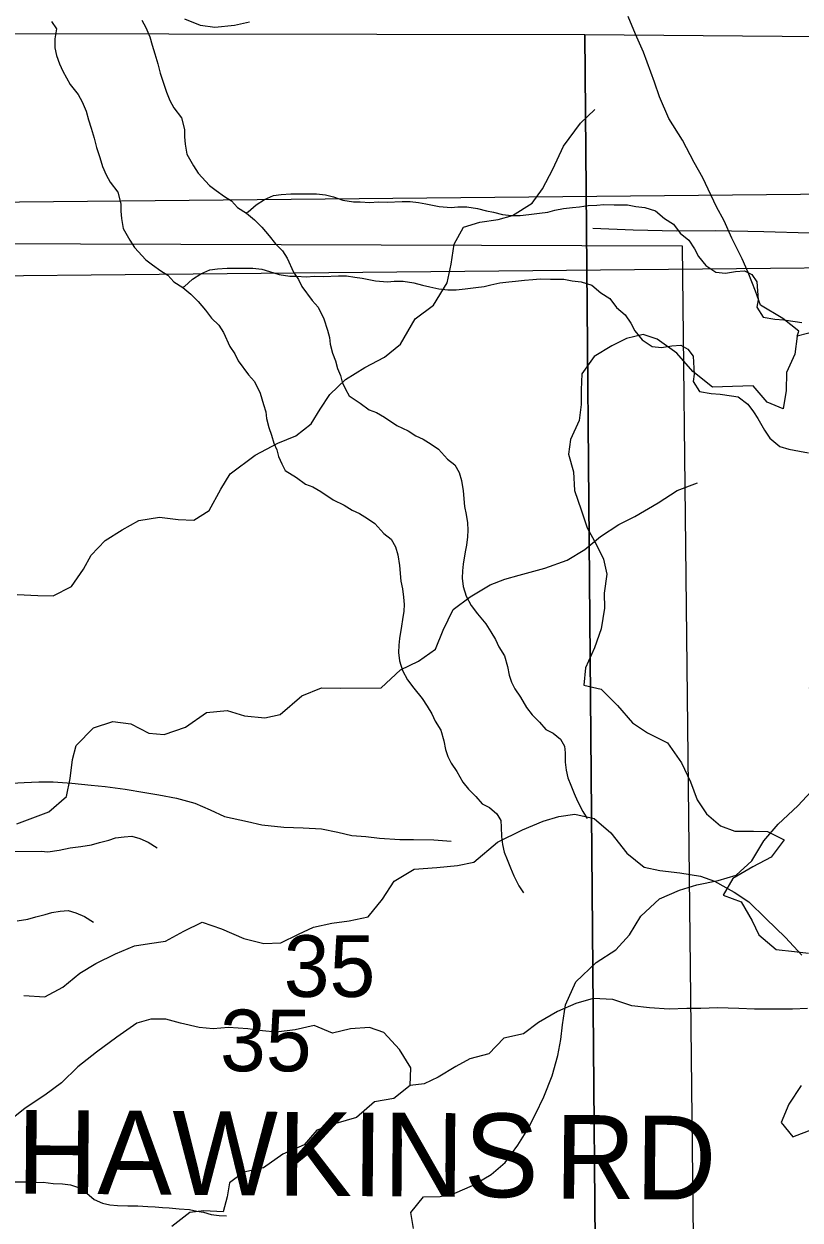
# Model space of a CAD drawing. Extents: x -21.1 to 50.3, y 0 to 22.1.
# Drawn here: x 7.069 to 7.596, y 19.342 to 20.155 of the extents above; entities that cross this region are included whole.
import ezdxf

# ---------------------------------------------------------------- set-up
doc = ezdxf.new("R2010")
doc.units = 0
for name, color, linetype in [('GM_X_City_Street', 7, 'Continuous'), ('GM_X_Major_Lake', 7, 'Continuous'), ('GM_X_Minor_River', 7, 'Continuous'), ('GM_X_Section', 7, 'Continuous'), ('GM_X_Section_Text', 7, 'Continuous'), ('GM_X_Township_Road_Text', 7, 'Continuous')]:
    doc.layers.add(name, color=color, linetype=linetype)

msp = doc.modelspace()

# ---------------------------------------------------------------- linework, layer by layer
at = {"layer": 'GM_X_City_Street'}
msp.add_lwpolyline([(7.45524, 20.01596), (7.48275, 20.01484), (7.51234, 20.01417), (7.53874, 20.01437), (7.57151, 20.01373), (7.60253, 20.01277), (7.652, 20.01277), (7.66218, 20.01262), (7.69033, 20.01023), (7.70354, 20.00864), (7.71849, 20.00673), (7.72771, 20.0053), (7.7573, 20.00403), (7.80725, 20.00418)], dxfattribs=at)
at = {"layer": 'GM_X_Major_Lake'}
for points in [[(7.60818, 19.94633), (7.59416, 19.94253), (7.59263, 19.9304), (7.58694, 19.91788), (7.58656, 19.90574), (7.58465, 19.89323), (7.57366, 19.89778), (7.56419, 19.90877), (7.55017, 19.90839), (7.53652, 19.90801), (7.52326, 19.91863), (7.51227, 19.93115), (7.49901, 19.94062), (7.48954, 19.94366), (7.47816, 19.941), (7.4683, 19.93607), (7.45617, 19.92886), (7.44783, 19.9171), (7.44744, 19.90611), (7.44743, 19.89624), (7.44591, 19.88525), (7.44022, 19.87235), (7.4387, 19.86249), (7.4421, 19.85035), (7.44285, 19.83783), (7.4474, 19.82456)], [(7.4474, 19.82456), (7.45156, 19.81243), (7.45762, 19.80143), (7.46254, 19.79119), (7.46481, 19.78095), (7.46291, 19.76805), (7.46328, 19.75781), (7.461, 19.74378), (7.45644, 19.73088), (7.45037, 19.71723), (7.44923, 19.70547), (7.46098, 19.70282), (7.47196, 19.69182), (7.48219, 19.68006), (7.49242, 19.67324), (7.50606, 19.66641), (7.51553, 19.65276), (7.52159, 19.63987), (7.52613, 19.62773), (7.53257, 19.61825), (7.54204, 19.6099), (7.5519, 19.60649), (7.56441, 19.60649), (7.57388, 19.60612), (7.58525, 19.60043), (7.57653, 19.58867), (7.56402, 19.58222), (7.55036, 19.57426), (7.54392, 19.56288), (7.55604, 19.55833), (7.56362, 19.54543), (7.56816, 19.53595), (7.57991, 19.52609), (7.59242, 19.52458), (7.60189, 19.52344)], [(7.59691, 19.43355), (7.58857, 19.42103), (7.58325, 19.40852), (7.59121, 19.39866), (7.60486, 19.40397)]]:
    msp.add_lwpolyline(points, dxfattribs=at)
at = {"layer": 'GM_X_Minor_River'}
for points in [[(7.59416, 19.94253), (7.59529, 19.94595), (7.58431, 19.95467), (7.56915, 19.96377), (7.56574, 19.97325), (7.56082, 19.98576), (7.55666, 19.99525), (7.54984, 20.00928), (7.54454, 20.02103), (7.53924, 20.03052), (7.53015, 20.05024), (7.52409, 20.06048), (7.51614, 20.07565), (7.50705, 20.09044), (7.50062, 20.10523), (7.49721, 20.11509), (7.48964, 20.13557), (7.48434, 20.1477), (7.47942, 20.15984)], [(7.08744, 20.1564), (7.09089, 20.15149), (7.08978, 20.14464), (7.08982, 20.13856), (7.09099, 20.13325), (7.09293, 20.12756), (7.09524, 20.12264), (7.10024, 20.11355), (7.1056, 20.10674), (7.1083, 20.10181), (7.111, 20.09537), (7.11255, 20.08968), (7.11449, 20.08399), (7.11643, 20.07717), (7.11799, 20.07072), (7.12031, 20.06389), (7.12224, 20.05782), (7.12456, 20.05214), (7.12725, 20.04721), (7.13262, 20.0404), (7.13457, 20.03244), (7.1346, 20.0275), (7.135, 20.02256), (7.13618, 20.01573), (7.14079, 20.00778), (7.14387, 20.00286), (7.15153, 19.99454), (7.15612, 19.99115), (7.16185, 19.987), (7.16643, 19.98399), (7.17064, 19.97945), (7.17676, 19.97569), (7.18211, 19.97116), (7.18709, 19.96625), (7.19207, 19.96019), (7.19629, 19.9549), (7.20126, 19.94999), (7.20433, 19.94507), (7.20857, 19.93559), (7.21203, 19.93068), (7.21434, 19.92575), (7.22124, 19.91629), (7.22546, 19.91175), (7.22931, 19.9038), (7.23163, 19.89621), (7.23318, 19.89128), (7.23359, 19.88673), (7.23515, 19.88065), (7.23708, 19.87535), (7.23863, 19.87004), (7.24056, 19.86549), (7.24173, 19.86094), (7.24404, 19.85601), (7.24635, 19.85147), (7.25399, 19.84657), (7.2601, 19.84204), (7.26506, 19.84017), (7.27041, 19.83716), (7.27882, 19.83151), (7.28645, 19.82775), (7.2918, 19.82436), (7.29676, 19.82211), (7.30211, 19.81872), (7.30707, 19.81533), (7.3132, 19.80853)], [(7.14889, 20.15725), (7.15158, 20.15233), (7.15429, 20.14589), (7.15584, 20.1402), (7.15778, 20.13451), (7.15972, 20.12768), (7.16127, 20.12123), (7.1636, 20.11441), (7.16553, 20.10834), (7.16785, 20.10265), (7.17054, 20.09773), (7.17591, 20.09092), (7.17786, 20.08295), (7.17788, 20.07802), (7.17829, 20.07308), (7.17947, 20.06625), (7.18408, 20.0583), (7.18716, 20.05337), (7.19482, 20.04506), (7.1994, 20.04166), (7.20514, 20.03752), (7.20972, 20.0345), (7.21393, 20.02997), (7.22004, 20.0262), (7.2254, 20.02167), (7.23038, 20.01676), (7.23536, 20.01071), (7.23958, 20.00542), (7.24455, 20.00051), (7.24762, 19.99559), (7.25186, 19.98611), (7.25532, 19.98119), (7.25763, 19.97627), (7.26453, 19.9668), (7.26875, 19.96227), (7.2726, 19.95431), (7.27492, 19.94673), (7.27647, 19.9418), (7.27688, 19.93724), (7.27844, 19.93117), (7.28037, 19.92586), (7.28192, 19.92055), (7.28385, 19.91601), (7.28502, 19.91145), (7.28733, 19.90653), (7.28964, 19.90198), (7.29728, 19.89709), (7.30339, 19.89256), (7.30835, 19.89069), (7.3137, 19.88768), (7.32211, 19.88202), (7.32974, 19.87827), (7.33509, 19.87488), (7.34005, 19.87263), (7.3454, 19.86924), (7.35036, 19.86585), (7.35649, 19.85904)], [(7.22203, 20.15602), (7.21179, 20.15374), (7.19853, 20.15222), (7.18867, 20.15374), (7.17806, 20.15791)], [(7.06425, 19.76717), (7.07829, 19.76655), (7.08854, 19.76626), (7.10101, 19.77246), (7.10925, 19.78432), (7.11447, 19.79386), (7.12387, 19.80383), (7.13557, 19.81116), (7.1469, 19.81735), (7.16092, 19.81976), (7.17346, 19.81798), (7.18409, 19.8177), (7.19465, 19.82426), (7.20249, 19.83877), (7.20885, 19.84909), (7.22581, 19.86179), (7.2413, 19.86991), (7.2534, 19.87497), (7.26395, 19.88305), (7.26993, 19.89298), (7.27667, 19.90293), (7.28721, 19.91328), (7.30042, 19.92139), (7.31364, 19.92835), (7.32456, 19.9372), (7.33465, 19.95439), (7.34709, 19.96362), (7.35644, 19.97891), (7.35899, 19.99147), (7.36114, 20.00517), (7.36749, 20.01664), (7.37846, 20.02016), (7.39097, 20.02179), (7.40081, 20.02455), (7.41402, 20.03303), (7.42114, 20.0426), (7.42823, 20.05596), (7.4353, 20.07161), (7.44693, 20.0873), (7.45671, 20.09651)], [(7.21973, 20.02639), (7.22118, 20.02697), (7.22648, 20.03194), (7.23218, 20.03539), (7.23825, 20.03808), (7.24358, 20.03887), (7.25004, 20.03929), (7.26755, 20.03938), (7.27365, 20.03866), (7.27899, 20.03717), (7.28547, 20.03492), (7.29271, 20.03382), (7.29728, 20.03385), (7.30375, 20.0335), (7.30946, 20.03392), (7.31555, 20.03357), (7.32583, 20.03401), (7.33115, 20.03404), (7.33687, 20.03331), (7.34182, 20.03257), (7.35097, 20.03073), (7.35897, 20.03001), (7.36353, 20.03041), (7.36962, 20.03045), (7.37686, 20.02935), (7.38296, 20.02786), (7.38791, 20.02675), (7.39401, 20.02527), (7.40011, 20.02454), (7.40582, 20.02457), (7.4119, 20.02537), (7.41913, 20.02616), (7.42484, 20.02696), (7.4294, 20.02812), (7.43548, 20.02929), (7.44157, 20.03009), (7.44614, 20.03049), (7.45222, 20.03129), (7.45793, 20.0317), (7.46288, 20.0321), (7.46973, 20.03176), (7.47886, 20.03181), (7.48458, 20.0307), (7.49067, 20.02998), (7.49792, 20.02774), (7.50404, 20.02246), (7.51015, 20.01869), (7.51475, 20.01264), (7.52049, 20.00773), (7.52433, 20.00205), (7.52702, 19.99675), (7.53201, 19.9907), (7.53888, 19.98618), (7.54536, 19.98545), (7.5522, 19.98663), (7.55829, 19.98704), (7.56325, 19.98441), (7.56671, 19.97949), (7.56754, 19.96734), (7.5668, 19.9624), (7.57103, 19.95558), (7.57903, 19.95411), (7.58512, 19.95376), (7.59274, 19.95266), (7.59731, 19.95193)], [(7.17645, 19.97588), (7.17789, 19.97645), (7.1832, 19.98142), (7.18889, 19.98487), (7.19496, 19.98757), (7.20029, 19.98835), (7.20676, 19.98877), (7.22427, 19.98887), (7.23036, 19.98814), (7.2357, 19.98665), (7.24218, 19.98441), (7.24942, 19.98331), (7.25399, 19.98333), (7.26046, 19.98299), (7.26617, 19.9834), (7.27226, 19.98305), (7.28254, 19.98349), (7.28787, 19.98352), (7.29358, 19.98279), (7.29853, 19.98206), (7.30768, 19.98021), (7.31568, 19.9795), (7.32024, 19.9799), (7.32633, 19.97993), (7.33357, 19.97883), (7.33967, 19.97735), (7.34463, 19.97624), (7.35072, 19.97475), (7.35682, 19.97402), (7.36253, 19.97406), (7.36862, 19.97485), (7.37584, 19.97565), (7.38155, 19.97644), (7.38611, 19.9776), (7.39219, 19.97878), (7.39828, 19.97957), (7.40285, 19.97998), (7.40893, 19.98077), (7.41464, 19.98118), (7.41959, 19.98159), (7.42644, 19.98125), (7.43558, 19.9813), (7.44129, 19.98019), (7.44738, 19.97946), (7.45463, 19.97722), (7.46075, 19.97194), (7.46686, 19.96817), (7.47146, 19.96212), (7.4772, 19.95721), (7.48104, 19.95154), (7.48373, 19.94623), (7.48872, 19.94018), (7.49559, 19.93566), (7.50207, 19.93494), (7.50891, 19.93611), (7.515, 19.93653), (7.51996, 19.9339), (7.52342, 19.92898), (7.52425, 19.91682), (7.52351, 19.91188), (7.52774, 19.90507), (7.53574, 19.90359), (7.54183, 19.90325), (7.54945, 19.90215), (7.55402, 19.90141), (7.56052, 19.89651), (7.56436, 19.89121), (7.56743, 19.88667), (7.57204, 19.87872), (7.5755, 19.87342), (7.58238, 19.86776), (7.58848, 19.86589), (7.59572, 19.86441), (7.60182, 19.86331)], [(7.35649, 19.85904), (7.36146, 19.85527), (7.36454, 19.84997), (7.36609, 19.84466), (7.36727, 19.83745), (7.36809, 19.82682), (7.36926, 19.8215), (7.37005, 19.81581), (7.37047, 19.81087), (7.37011, 19.80631), (7.36938, 19.80061), (7.36864, 19.79605), (7.36717, 19.78768), (7.36681, 19.78312), (7.36646, 19.77818), (7.36725, 19.77249), (7.36919, 19.76604), (7.37265, 19.7596), (7.37687, 19.75392), (7.38262, 19.74712), (7.38608, 19.74182), (7.38915, 19.73652), (7.39146, 19.73159), (7.3953, 19.72553), (7.39724, 19.71833), (7.39842, 19.71225), (7.39997, 19.7077), (7.40228, 19.70316), (7.40612, 19.69748), (7.41034, 19.69029), (7.41418, 19.68537), (7.41915, 19.68046), (7.42337, 19.67554), (7.42833, 19.67291), (7.4333, 19.66876), (7.43599, 19.66422), (7.4364, 19.65966), (7.43643, 19.6532), (7.43723, 19.64789), (7.4384, 19.64258), (7.44033, 19.63765), (7.44264, 19.63196), (7.44496, 19.62666), (7.44842, 19.61984), (7.45149, 19.61491)], [(7.06398, 19.61125), (7.08568, 19.61956), (7.09773, 19.62993), (7.10028, 19.64212), (7.10168, 19.65505), (7.10425, 19.66457), (7.11591, 19.67646), (7.12915, 19.68077), (7.14131, 19.67936), (7.15351, 19.67302), (7.16414, 19.67198), (7.17852, 19.67705), (7.19285, 19.68707), (7.20688, 19.68834), (7.21867, 19.68465), (7.23235, 19.68326), (7.24295, 19.68564), (7.25764, 19.69832), (7.27087, 19.70376), (7.28416, 19.70351), (7.31148, 19.70376), (7.32465, 19.71605), (7.33674, 19.72186), (7.34843, 19.72995), (7.35363, 19.74292), (7.36033, 19.75704), (7.37202, 19.76551), (7.38561, 19.77362), (7.39544, 19.77751), (7.40528, 19.78026), (7.4227, 19.78498), (7.43783, 19.79045), (7.4499, 19.79778), (7.46045, 19.80662), (7.4729, 19.81471), (7.48386, 19.82014), (7.49971, 19.82941), (7.51254, 19.83789), (7.52653, 19.84296)], [(7.3132, 19.80853), (7.31817, 19.80475), (7.32125, 19.79945), (7.3228, 19.79415), (7.32398, 19.78693), (7.3248, 19.7763), (7.32597, 19.77099), (7.32677, 19.76529), (7.32718, 19.76036), (7.32682, 19.7558), (7.32609, 19.75009), (7.32535, 19.74553), (7.32388, 19.73717), (7.32352, 19.73261), (7.32317, 19.72766), (7.32396, 19.72197), (7.3259, 19.71552), (7.32936, 19.70908), (7.33358, 19.70341), (7.33933, 19.6966), (7.34279, 19.6913), (7.34586, 19.686), (7.34817, 19.68107), (7.35201, 19.67502), (7.35395, 19.66781), (7.35513, 19.66174), (7.35668, 19.65719), (7.35899, 19.65264), (7.36283, 19.64697), (7.36705, 19.63977), (7.37089, 19.63485), (7.37586, 19.62994), (7.38008, 19.62503), (7.38504, 19.6224), (7.39001, 19.61824), (7.3927, 19.6137), (7.39311, 19.60914), (7.39315, 19.60268), (7.39394, 19.59737), (7.39511, 19.59206), (7.39704, 19.58713), (7.39935, 19.58144), (7.40167, 19.57614), (7.40513, 19.56932), (7.4082, 19.5644)], [(7.57156, 19.59988), (7.58117, 19.61118), (7.59458, 19.62358), (7.60686, 19.63675), (7.61271, 19.65189), (7.61281, 19.66138), (7.6095, 19.67167), (7.60771, 19.68233), (7.60592, 19.6926), (7.60262, 19.70365)], [(7.05572, 19.63867), (7.06899, 19.63943), (7.07885, 19.63981), (7.0887, 19.63982), (7.10121, 19.63906), (7.11448, 19.63754), (7.12395, 19.63679), (7.1376, 19.63489), (7.15087, 19.63262), (7.16034, 19.6311), (7.17247, 19.62883), (7.18498, 19.62541), (7.19521, 19.62087), (7.20506, 19.61631), (7.2206, 19.6129), (7.23046, 19.61063), (7.24524, 19.60912), (7.25851, 19.60873), (7.27101, 19.60798), (7.28201, 19.6057), (7.29148, 19.60343), (7.30096, 19.60267), (7.31043, 19.60154), (7.32408, 19.60078), (7.33356, 19.60078), (7.3472, 19.6004), (7.35895, 19.59964)], [(7.06859, 19.49477), (7.08302, 19.49377), (7.0951, 19.50034), (7.10678, 19.50995), (7.11772, 19.51651), (7.13095, 19.52309), (7.1438, 19.52853), (7.15403, 19.53015), (7.16502, 19.53177), (7.17749, 19.53835), (7.18995, 19.54455), (7.2029, 19.54011), (7.21814, 19.53342), (7.23183, 19.53012), (7.24321, 19.53061), (7.2553, 19.53642), (7.2655, 19.54108), (7.278, 19.54386), (7.28975, 19.54549), (7.30263, 19.54827), (7.31239, 19.56014), (7.32025, 19.57237), (7.33383, 19.58048), (7.34938, 19.58177), (7.36341, 19.58304), (7.37439, 19.58542), (7.39059, 19.59887), (7.40759, 19.60739), (7.42158, 19.61322), (7.43218, 19.61636), (7.44317, 19.61799), (7.4561, 19.61507), (7.46757, 19.6053), (7.47832, 19.59134), (7.49017, 19.58195), (7.50081, 19.57977), (7.51449, 19.578), (7.52855, 19.57585), (7.53807, 19.57252), (7.55142, 19.56505), (7.56134, 19.5583), (7.57283, 19.54701), (7.58623, 19.53421), (7.59734, 19.52216)], [(7.05383, 19.59258), (7.08047, 19.59273), (7.08504, 19.59238), (7.09265, 19.59356), (7.10026, 19.59512), (7.10748, 19.59592), (7.11471, 19.5971), (7.12003, 19.59865), (7.12649, 19.6002), (7.13105, 19.60175), (7.13676, 19.60254), (7.14208, 19.60295), (7.14742, 19.60146), (7.15315, 19.59883), (7.15926, 19.59506)], [(7.33349, 19.33639), (7.3317, 19.34743), (7.34016, 19.35798), (7.35156, 19.35824), (7.36145, 19.36042), (7.37365, 19.36561), (7.38625, 19.37308), (7.39583, 19.38134), (7.4043, 19.39303), (7.41125, 19.40398), (7.41629, 19.41418), (7.4221, 19.4259), (7.42756, 19.44028), (7.4315, 19.45392), (7.43351, 19.46491), (7.43475, 19.47477), (7.43679, 19.48843), (7.44378, 19.50393), (7.45758, 19.51709), (7.47096, 19.52569), (7.48017, 19.53585), (7.4879, 19.54869), (7.50055, 19.56034), (7.51427, 19.56628), (7.52608, 19.56996), (7.54053, 19.57285), (7.55272, 19.57652), (7.56345, 19.58629), (7.57156, 19.59988)], [(7.0642, 19.5454), (7.07142, 19.54658), (7.07674, 19.54813), (7.0832, 19.54969), (7.08776, 19.55123), (7.09347, 19.55202), (7.0988, 19.55243), (7.10413, 19.55094), (7.10986, 19.54831), (7.11597, 19.54455)], [(7.60111, 19.48589), (7.59088, 19.48551), (7.5651, 19.48551), (7.55449, 19.48589), (7.54008, 19.48626), (7.52871, 19.48588), (7.51924, 19.48588), (7.5071, 19.4855), (7.49384, 19.48626), (7.48171, 19.48777), (7.46882, 19.49194), (7.45556, 19.4927), (7.4438, 19.48929), (7.43129, 19.48397), (7.4184, 19.47639), (7.40816, 19.4688), (7.39489, 19.46576), (7.38465, 19.45515), (7.37176, 19.45173), (7.36228, 19.44642), (7.35015, 19.43921), (7.34067, 19.43466), (7.33119, 19.43352), (7.3202, 19.42479), (7.30693, 19.42252), (7.29479, 19.4119), (7.28076, 19.40772), (7.26787, 19.40317), (7.25915, 19.39331), (7.24474, 19.38686), (7.23147, 19.37776), (7.2182, 19.37472), (7.20834, 19.36751), (7.20682, 19.35803), (7.20416, 19.34779), (7.1909, 19.34855), (7.18142, 19.34741), (7.16928, 19.33793)], [(7.33119, 19.43352), (7.33158, 19.44566), (7.324, 19.45817), (7.3134, 19.46955), (7.30354, 19.47296), (7.29065, 19.4722), (7.27852, 19.46917), (7.26602, 19.47447), (7.25313, 19.47144), (7.24024, 19.46992), (7.23076, 19.47068), (7.22091, 19.47219), (7.20764, 19.47295), (7.1974, 19.47219), (7.18793, 19.47295), (7.17504, 19.47598), (7.16519, 19.47863), (7.15495, 19.47863), (7.14547, 19.47598), (7.13183, 19.46649), (7.11817, 19.45625), (7.10528, 19.44639), (7.09428, 19.43539), (7.0829, 19.42704), (7.06963, 19.41832), (7.05674, 19.4077)], [(7.05698, 19.36808), (7.06993, 19.36816), (7.07678, 19.36781), (7.08173, 19.36784), (7.08858, 19.36712), (7.09506, 19.36677), (7.10039, 19.36604), (7.10649, 19.36418), (7.11146, 19.36041), (7.11643, 19.35625), (7.12216, 19.35363), (7.12711, 19.35252), (7.13244, 19.35216), (7.1393, 19.35182), (7.14615, 19.35186), (7.153, 19.35152), (7.15795, 19.35116), (7.1629, 19.35081), (7.16747, 19.35046), (7.17433, 19.34974), (7.18118, 19.34939), (7.18614, 19.34828), (7.19071, 19.34755), (7.19605, 19.34606), (7.20138, 19.34533), (7.20633, 19.34498)]]:
    msp.add_lwpolyline(points, dxfattribs=at)
at = {"layer": 'GM_X_Section'}
for points in [[(6.46064, 20.14904), (7.44997, 20.14748), (7.45853, 19.14217), (6.46467, 19.14528)], [(7.44997, 20.14748), (8.46844, 20.13891), (8.46716, 19.13592), (7.45853, 19.14217)], [(6.88082, 20.03211), (7.89619, 20.04203), (7.90002, 19.02624), (7.83142, 19.02525), (6.88772, 19.01332)], [(6.49363, 20.00748), (7.51608, 20.00403), (7.5274, 18.98311), (6.50457, 18.98884)], [(6.83753, 19.9816), (7.8529, 19.99152), (7.85673, 18.97573), (7.78814, 18.97473), (6.84443, 18.96281)]]:
    msp.add_lwpolyline(points, close=True, dxfattribs=at)

# ---------------------------------------------------------------- texts
at = {"layer": 'GM_X_Section_Text'}
for p in [(7.24526, 19.4938), (7.20197, 19.44328)]:
    msp.add_text('35', height=0.041856, rotation=0.00001, dxfattribs=at).set_placement(p)
at = {"layer": 'GM_X_Township_Road_Text'}
for s, rotation, p in [('HAWKINS', 359.56483, (7.06369, 19.36025)), ('RD', 359.50448, (7.42922, 19.35691))]:
    msp.add_text(s, height=0.056818, rotation=rotation, dxfattribs=at).set_placement(p)

doc.saveas('drawing.dxf')
